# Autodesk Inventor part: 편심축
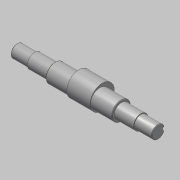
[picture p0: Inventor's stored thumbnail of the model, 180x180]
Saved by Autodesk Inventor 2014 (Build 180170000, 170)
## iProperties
Created: 2015-10
Part Number: 편심축
Document SubType Name: Modeling
Designer: mdu
Density: 1 g/cm^3
Material: 강철, 연강
Mass: 168.947 g
Surface Area: 248.524 cm^2
Volume: 168.947 cm^3
Appearance: 강철
Author: mdu
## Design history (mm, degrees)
sketch "스케치1"
  geometry: L1 (-20.5, -41.331)-(-20.5, 32.669) reference; L2 (7.5, -30.031)-(7.5, 21.369) reference; L3 (135.5, -30.331)-(135.5, 21.669) reference; L4 (121.5, 21.369)-(121.5, -30.031) reference; L5 (184.5, -4.331)-(-57.5, -4.331); L6 (184.5, -4.331)-(184.5, 6.669); L7 (154.5, 8.169)-(121.5, 8.169); L8 (121.5, 8.169)-(121.5, 11.669); L9 (121.5, 11.669)-(7.5, 11.669); L10 (7.5, 11.669)-(7.5, 8.169); L11 (7.5, 8.169)-(-27.5, 8.169); L12 (-27.5, 8.169)-(-27.5, 6.669); L13 (-27.5, 6.669)-(-57.5, 6.669); L14 (-57.5, 6.669)-(-57.5, -4.331); L15 (154.5, 8.169)-(154.5, 6.669); L16 (154.5, 6.669)-(184.5, 6.669); C1 r 32.5 at (64.5, -4.331) reference; 1 further point
  constraints: 24 end point, 8 perpendicular, 5 point on line, 3 parallel, 2 collinear
  dimensions: "d1" = 25 diameter of L11 L5; "d2" = 32 diameter of L9 L5; "d3" = 22 diameter of L13 L5; "d4" = 35 distance of L10.end L11.end; "d5" = 30 distance of L12.end L13.end; "d15" = 33 distance of L7.start L7.end; "d26" = 30 distance of L15.end L6.end
revolve "회전1" sketch "스케치1" stored, may be unused: angle "d6" = 90 deg
node "작업 평면1"
sketch "스케치2"
  geometry: C1 r 16 at (0, 0) reference; C2 r 20.75 at (0, 4)
  constraints: 1 centre point, 1 vertical alignment
  dimensions: "d34" = 4 distance of C2.centre C1.centre; "d35" = 41.5 diameter of C2
extrude "돌출1" join sketch "스케치2" stored distance "d9" = 40; taper "d10" = 0 deg
chamfer "모따기1" distance "d11" = 1; stored, may be unused: second distance "d12" = 2, angle "d13" = 45 deg
node "작업 평면2"
sketch "스케치3"
  geometry: L1 (-15, -10)-(-15, 10) reference; L2 (-15, 3)-(0, 3); L3 (0, -3)-(-15, -3); A1 r 3 centre (0, 0) between (0, -3) and (0, 3); 2 further points
  constraints: 4 end point, 2 perpendicular, 2 point on circle, 2 point on line, 2 tangent, 1 centre point, 1 horizontal alignment, 1 midpoint
  dimensions: "d16" = 18 dimension on A1 L1; "d17" = 6 distance between parallel lines of L3 L2
extrude "돌출2" cut sketch "스케치3" distance "d18" = 3.5; taper "d19" = 0 deg
node "작업 평면3"
node "솔리드1"
mirror "대칭1"
node "참조1"
node "참조2"
node "참조3"
node "참조4"
node "참조5"
other parameters: "d30" = 35
